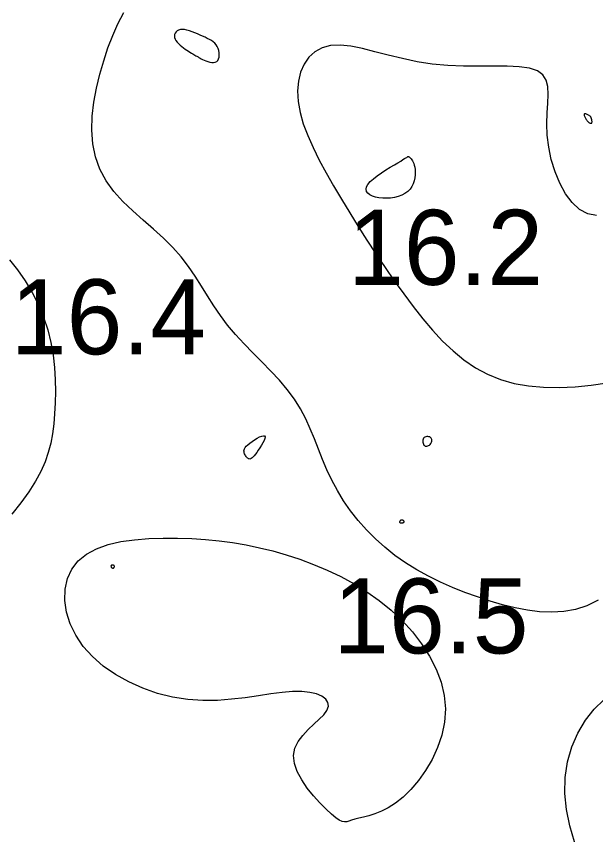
# Model space of a CAD drawing. Extents: x 3040093 to 3056816, y 408076 to 509144.
# Drawn here: x 3045557.4 to 3045596, y 434288.8 to 434343.4 of the extents above; entities that cross this region are included whole.
import ezdxf

# ---------------------------------------------------------------- set-up
doc = ezdxf.new("R2010")
doc.units = 0
doc.layers.add('V-CHAN-CONT-EL17', color=7, linetype='Continuous')
doc.layers.add('V-TOPO-SOUN-0610', color=7, linetype='Continuous')

msp = doc.modelspace()

# ---------------------------------------------------------------- linework, layer by layer
at = {"layer": 'V-CHAN-CONT-EL17'}
for points in [[(3045596.195, 434304.462), (3045595.445, 434304.104), (3045594.676, 434303.857), (3045593.893, 434303.714), (3045593.097, 434303.664), (3045592.29, 434303.696), (3045591.474, 434303.798), (3045590.65, 434303.959), (3045589.819, 434304.168), (3045588.984, 434304.414), (3045588.148, 434304.688), (3045587.313, 434304.989), (3045586.487, 434305.32), (3045585.673, 434305.68), (3045584.877, 434306.073), (3045584.104, 434306.499), (3045583.359, 434306.961), (3045582.648, 434307.459), (3045581.974, 434307.995), (3045581.34, 434308.565), (3045580.747, 434309.165), (3045580.196, 434309.79), (3045579.689, 434310.437), (3045579.226, 434311.1), (3045578.809, 434311.776), (3045578.44, 434312.461), (3045578.116, 434313.15), (3045577.825, 434313.84), (3045577.553, 434314.53), (3045577.285, 434315.216), (3045577.004, 434315.896), (3045576.697, 434316.568), (3045576.348, 434317.228), (3045575.942, 434317.875), (3045575.47, 434318.508), (3045574.942, 434319.128), (3045574.374, 434319.74), (3045573.782, 434320.347), (3045573.182, 434320.953), (3045572.589, 434321.563), (3045572.021, 434322.179), (3045571.492, 434322.806), (3045571.013, 434323.446), (3045570.573, 434324.096), (3045570.156, 434324.752), (3045569.746, 434325.41), (3045569.325, 434326.067), (3045568.878, 434326.717), (3045568.388, 434327.358), (3045567.839, 434327.984), (3045567.221, 434328.594), (3045566.553, 434329.196), (3045565.862, 434329.799), (3045565.174, 434330.415), (3045564.514, 434331.052), (3045563.91, 434331.722), (3045563.386, 434332.433), (3045562.97, 434333.196), (3045562.68, 434334.018), (3045562.51, 434334.889), (3045562.445, 434335.796), (3045562.473, 434336.727), (3045562.579, 434337.669), (3045562.751, 434338.609), (3045562.973, 434339.534), (3045563.232, 434340.432), (3045563.518, 434341.291), (3045563.833, 434342.113), (3045564.18, 434342.898), (3045564.564, 434343.649)], [(3045596.085, 434330.119), (3045595.494, 434330.23), (3045594.949, 434330.522), (3045594.454, 434330.977), (3045594.014, 434331.567), (3045593.634, 434332.259), (3045593.318, 434333.026), (3045593.069, 434333.836), (3045592.892, 434334.66), (3045592.792, 434335.467), (3045592.766, 434336.233), (3045592.789, 434336.945), (3045592.828, 434337.599), (3045592.851, 434338.187), (3045592.826, 434338.703), (3045592.721, 434339.141), (3045592.503, 434339.495), (3045592.142, 434339.757), (3045591.613, 434339.927), (3045590.934, 434340.02), (3045590.13, 434340.06), (3045589.226, 434340.066), (3045588.25, 434340.062), (3045587.225, 434340.068), (3045586.179, 434340.106), (3045585.137, 434340.198), (3045584.122, 434340.357), (3045583.142, 434340.566), (3045582.204, 434340.799), (3045581.313, 434341.032), (3045580.477, 434341.237), (3045579.7, 434341.392), (3045578.988, 434341.468), (3045578.349, 434341.442), (3045577.786, 434341.295), (3045577.303, 434341.031), (3045576.902, 434340.665), (3045576.585, 434340.207), (3045576.353, 434339.67), (3045576.21, 434339.068), (3045576.156, 434338.411), (3045576.194, 434337.713), (3045576.323, 434336.984), (3045576.538, 434336.227), (3045576.828, 434335.444), (3045577.184, 434334.637), (3045577.596, 434333.807), (3045578.057, 434332.956), (3045578.555, 434332.086), (3045579.083, 434331.198), (3045579.631, 434330.294), (3045580.198, 434329.381), (3045580.78, 434328.463), (3045581.376, 434327.549), (3045581.985, 434326.642), (3045582.603, 434325.751), (3045583.231, 434324.881), (3045583.865, 434324.038), (3045584.505, 434323.228), (3045585.156, 434322.461), (3045585.825, 434321.742), (3045586.519, 434321.082), (3045587.244, 434320.486), (3045588.008, 434319.965), (3045588.816, 434319.525), (3045589.675, 434319.175), (3045590.59, 434318.92), (3045591.554, 434318.754), (3045592.558, 434318.668), (3045593.594, 434318.653), (3045594.652, 434318.701), (3045595.724, 434318.803), (3045596.801, 434318.95)], [(3045556.955, 434327.16), (3045557.493, 434326.486), (3045558.002, 434325.753), (3045558.468, 434324.974), (3045558.882, 434324.162), (3045559.231, 434323.33), (3045559.507, 434322.488), (3045559.715, 434321.645), (3045559.862, 434320.807), (3045559.957, 434319.979), (3045560.006, 434319.169), (3045560.018, 434318.381), (3045559.999, 434317.624), (3045559.958, 434316.902), (3045559.9, 434316.22), (3045559.817, 434315.568), (3045559.7, 434314.937), (3045559.537, 434314.316), (3045559.321, 434313.692), (3045559.04, 434313.056), (3045558.685, 434312.396), (3045558.245, 434311.701), (3045557.716, 434310.967), (3045557.11, 434310.212)], [(3045596.55, 434284.32), (3045596.002, 434285.266), (3045595.487, 434286.261), (3045595.02, 434287.294), (3045594.619, 434288.355), (3045594.298, 434289.432), (3045594.075, 434290.516), (3045593.965, 434291.595), (3045593.985, 434292.659), (3045594.146, 434293.696), (3045594.436, 434294.688), (3045594.841, 434295.616), (3045595.343, 434296.463), (3045595.927, 434297.209), (3045596.577, 434297.835)]]:
    msp.add_lwpolyline(points, dxfattribs=at)
for points in [[(3045569.928, 434340.473), (3045570.046, 434340.424), (3045570.174, 434340.378), (3045570.306, 434340.339), (3045570.437, 434340.314), (3045570.561, 434340.306), (3045570.673, 434340.322), (3045570.768, 434340.366), (3045570.842, 434340.442), (3045570.894, 434340.545), (3045570.925, 434340.669), (3045570.936, 434340.807), (3045570.928, 434340.953), (3045570.902, 434341.101), (3045570.859, 434341.245), (3045570.799, 434341.377), (3045570.723, 434341.494), (3045570.633, 434341.596), (3045570.529, 434341.687), (3045570.411, 434341.769), (3045570.281, 434341.844), (3045570.14, 434341.916), (3045569.988, 434341.988), (3045569.827, 434342.062), (3045569.657, 434342.139), (3045569.482, 434342.218), (3045569.303, 434342.295), (3045569.125, 434342.365), (3045568.95, 434342.426), (3045568.782, 434342.474), (3045568.622, 434342.504), (3045568.475, 434342.514), (3045568.343, 434342.501), (3045568.228, 434342.466), (3045568.13, 434342.413), (3045568.052, 434342.344), (3045567.994, 434342.263), (3045567.958, 434342.172), (3045567.945, 434342.075), (3045567.956, 434341.973), (3045567.992, 434341.871), (3045568.051, 434341.769), (3045568.127, 434341.668), (3045568.219, 434341.568), (3045568.322, 434341.472), (3045568.432, 434341.379), (3045568.546, 434341.291), (3045568.66, 434341.209), (3045568.772, 434341.133), (3045568.879, 434341.063), (3045568.981, 434340.999), (3045569.077, 434340.941), (3045569.165, 434340.889), (3045569.246, 434340.843), (3045569.318, 434340.801), (3045569.381, 434340.765), (3045569.433, 434340.734), (3045569.479, 434340.705), (3045569.522, 434340.679), (3045569.565, 434340.653), (3045569.613, 434340.625), (3045569.67, 434340.595), (3045569.739, 434340.561), (3045569.824, 434340.52)], [(3045595.778, 434336.32), (3045595.782, 434336.351), (3045595.781, 434336.386), (3045595.778, 434336.424), (3045595.771, 434336.463), (3045595.763, 434336.503), (3045595.754, 434336.542), (3045595.743, 434336.578), (3045595.733, 434336.61), (3045595.721, 434336.639), (3045595.707, 434336.666), (3045595.692, 434336.69), (3045595.672, 434336.713), (3045595.649, 434336.736), (3045595.621, 434336.758), (3045595.588, 434336.78), (3045595.548, 434336.803), (3045595.505, 434336.826), (3045595.459, 434336.847), (3045595.413, 434336.866), (3045595.369, 434336.879), (3045595.33, 434336.888), (3045595.296, 434336.888), (3045595.271, 434336.881), (3045595.255, 434336.864), (3045595.249, 434336.839), (3045595.251, 434336.807), (3045595.26, 434336.769), (3045595.275, 434336.727), (3045595.294, 434336.683), (3045595.317, 434336.637), (3045595.343, 434336.592), (3045595.37, 434336.548), (3045595.398, 434336.506), (3045595.427, 434336.466), (3045595.457, 434336.429), (3045595.487, 434336.394), (3045595.518, 434336.363), (3045595.549, 434336.335), (3045595.58, 434336.311), (3045595.611, 434336.291), (3045595.641, 434336.276), (3045595.669, 434336.265), (3045595.696, 434336.259), (3045595.72, 434336.259), (3045595.741, 434336.264), (3045595.758, 434336.276), (3045595.77, 434336.295)], [(3045580.991, 434332.368), (3045581.206, 434332.562), (3045581.463, 434332.76), (3045581.747, 434332.957), (3045582.042, 434333.148), (3045582.333, 434333.327), (3045582.605, 434333.49), (3045582.843, 434333.63), (3045583.034, 434333.744), (3045583.182, 434333.834), (3045583.293, 434333.903), (3045583.372, 434333.954), (3045583.427, 434333.989), (3045583.463, 434334.012), (3045583.487, 434334.027), (3045583.504, 434334.035), (3045583.52, 434334.04), (3045583.537, 434334.041), (3045583.556, 434334.038), (3045583.576, 434334.029), (3045583.599, 434334.015), (3045583.625, 434333.993), (3045583.655, 434333.964), (3045583.69, 434333.927), (3045583.729, 434333.88), (3045583.772, 434333.823), (3045583.816, 434333.754), (3045583.859, 434333.671), (3045583.9, 434333.573), (3045583.936, 434333.459), (3045583.965, 434333.326), (3045583.985, 434333.175), (3045583.994, 434333.003), (3045583.99, 434332.817), (3045583.968, 434332.621), (3045583.927, 434332.422), (3045583.862, 434332.224), (3045583.772, 434332.034), (3045583.652, 434331.858), (3045583.5, 434331.701), (3045583.313, 434331.568), (3045583.099, 434331.459), (3045582.862, 434331.374), (3045582.609, 434331.312), (3045582.349, 434331.273), (3045582.086, 434331.257), (3045581.828, 434331.262), (3045581.581, 434331.289), (3045581.353, 434331.336), (3045581.149, 434331.403), (3045580.978, 434331.49), (3045580.845, 434331.595), (3045580.757, 434331.717), (3045580.721, 434331.857), (3045580.744, 434332.012), (3045580.833, 434332.183)], [(3045573.342, 434314.2), (3045573.26, 434314.099), (3045573.187, 434314.019), (3045573.122, 434313.958), (3045573.065, 434313.916), (3045573.012, 434313.891), (3045572.964, 434313.881), (3045572.919, 434313.885), (3045572.875, 434313.901), (3045572.833, 434313.928), (3045572.793, 434313.964), (3045572.755, 434314.008), (3045572.72, 434314.058), (3045572.686, 434314.113), (3045572.656, 434314.17), (3045572.628, 434314.23), (3045572.604, 434314.289), (3045572.587, 434314.351), (3045572.58, 434314.415), (3045572.588, 434314.483), (3045572.613, 434314.558), (3045572.661, 434314.639), (3045572.734, 434314.73), (3045572.837, 434314.83), (3045572.97, 434314.941), (3045573.126, 434315.057), (3045573.294, 434315.169), (3045573.464, 434315.27), (3045573.626, 434315.352), (3045573.769, 434315.409), (3045573.883, 434315.433), (3045573.957, 434315.416), (3045573.985, 434315.353), (3045573.97, 434315.252), (3045573.922, 434315.12), (3045573.847, 434314.966), (3045573.753, 434314.801), (3045573.647, 434314.633), (3045573.539, 434314.471), (3045573.435, 434314.324)], [(3045585.067, 434314.958), (3045585.091, 434315.014), (3045585.105, 434315.072), (3045585.11, 434315.129), (3045585.104, 434315.183), (3045585.088, 434315.234), (3045585.06, 434315.28), (3045585.02, 434315.318), (3045584.969, 434315.348), (3045584.91, 434315.368), (3045584.844, 434315.378), (3045584.777, 434315.378), (3045584.71, 434315.367), (3045584.648, 434315.346), (3045584.593, 434315.313), (3045584.549, 434315.267), (3045584.518, 434315.211), (3045584.501, 434315.145), (3045584.496, 434315.074), (3045584.502, 434315.002), (3045584.519, 434314.932), (3045584.545, 434314.868), (3045584.579, 434314.813), (3045584.621, 434314.771), (3045584.67, 434314.745), (3045584.723, 434314.735), (3045584.779, 434314.738), (3045584.835, 434314.753), (3045584.891, 434314.778), (3045584.944, 434314.813), (3045584.992, 434314.856), (3045585.033, 434314.904)], [(3045583.26, 434309.707), (3045583.256, 434309.718), (3045583.25, 434309.73), (3045583.243, 434309.741), (3045583.233, 434309.753), (3045583.222, 434309.765), (3045583.208, 434309.776), (3045583.192, 434309.786), (3045583.173, 434309.795), (3045583.153, 434309.803), (3045583.131, 434309.809), (3045583.108, 434309.812), (3045583.085, 434309.812), (3045583.063, 434309.809), (3045583.041, 434309.803), (3045583.02, 434309.792), (3045583.002, 434309.776), (3045582.986, 434309.757), (3045582.973, 434309.736), (3045582.964, 434309.714), (3045582.959, 434309.692), (3045582.96, 434309.671), (3045582.966, 434309.653), (3045582.979, 434309.638), (3045582.998, 434309.628), (3045583.022, 434309.623), (3045583.05, 434309.621), (3045583.081, 434309.622), (3045583.113, 434309.626), (3045583.144, 434309.631), (3045583.173, 434309.637), (3045583.199, 434309.643), (3045583.219, 434309.649), (3045583.236, 434309.655), (3045583.248, 434309.661), (3045583.256, 434309.667), (3045583.261, 434309.674), (3045583.264, 434309.681), (3045583.264, 434309.688), (3045583.263, 434309.697)], [(3045575.969, 434294.598), (3045576.187, 434295.047), (3045576.495, 434295.461), (3045576.857, 434295.844), (3045577.237, 434296.199), (3045577.598, 434296.529), (3045577.903, 434296.838), (3045578.116, 434297.128), (3045578.208, 434297.4), (3045578.178, 434297.651), (3045578.032, 434297.875), (3045577.779, 434298.066), (3045577.424, 434298.218), (3045576.974, 434298.325), (3045576.436, 434298.381), (3045575.817, 434298.38), (3045575.123, 434298.321), (3045574.362, 434298.22), (3045573.543, 434298.096), (3045572.672, 434297.97), (3045571.758, 434297.862), (3045570.808, 434297.792), (3045569.831, 434297.779), (3045568.833, 434297.845), (3045567.825, 434298.005), (3045566.822, 434298.258), (3045565.841, 434298.597), (3045564.899, 434299.017), (3045564.013, 434299.513), (3045563.2, 434300.078), (3045562.476, 434300.707), (3045561.86, 434301.393), (3045561.365, 434302.13), (3045560.996, 434302.899), (3045560.754, 434303.68), (3045560.641, 434304.456), (3045560.66, 434305.204), (3045560.812, 434305.907), (3045561.098, 434306.544), (3045561.521, 434307.096), (3045562.079, 434307.547), (3045562.755, 434307.904), (3045563.529, 434308.175), (3045564.381, 434308.371), (3045565.29, 434308.503), (3045566.237, 434308.578), (3045567.2, 434308.609), (3045568.161, 434308.604), (3045569.102, 434308.572), (3045570.024, 434308.512), (3045570.931, 434308.424), (3045571.828, 434308.305), (3045572.719, 434308.154), (3045573.608, 434307.97), (3045574.501, 434307.749), (3045575.4, 434307.492), (3045576.309, 434307.196), (3045577.223, 434306.858), (3045578.133, 434306.476), (3045579.034, 434306.047), (3045579.917, 434305.569), (3045580.776, 434305.038), (3045581.603, 434304.454), (3045582.39, 434303.812), (3045583.131, 434303.112), (3045583.813, 434302.36), (3045584.425, 434301.565), (3045584.955, 434300.734), (3045585.39, 434299.877), (3045585.719, 434299.001), (3045585.93, 434298.114), (3045586.009, 434297.225), (3045585.952, 434296.342), (3045585.771, 434295.477), (3045585.487, 434294.643), (3045585.118, 434293.851), (3045584.684, 434293.113), (3045584.205, 434292.442), (3045583.699, 434291.85), (3045583.187, 434291.35), (3045582.684, 434290.948), (3045582.2, 434290.636), (3045581.739, 434290.4), (3045581.307, 434290.226), (3045580.908, 434290.1), (3045580.549, 434290.008), (3045580.234, 434289.937), (3045579.969, 434289.873), (3045579.756, 434289.805), (3045579.582, 434289.744), (3045579.43, 434289.701), (3045579.282, 434289.689), (3045579.124, 434289.722), (3045578.938, 434289.811), (3045578.708, 434289.97), (3045578.416, 434290.212), (3045578.054, 434290.544), (3045577.645, 434290.955), (3045577.218, 434291.427), (3045576.804, 434291.943), (3045576.433, 434292.487), (3045576.135, 434293.041), (3045575.94, 434293.588), (3045575.878, 434294.112)], [(3045563.91, 434306.784), (3045563.892, 434306.794), (3045563.87, 434306.803), (3045563.847, 434306.809), (3045563.824, 434306.813), (3045563.801, 434306.814), (3045563.78, 434306.812), (3045563.761, 434306.806), (3045563.746, 434306.796), (3045563.734, 434306.783), (3045563.725, 434306.767), (3045563.721, 434306.75), (3045563.719, 434306.731), (3045563.721, 434306.711), (3045563.726, 434306.692), (3045563.734, 434306.674), (3045563.746, 434306.657), (3045563.759, 434306.642), (3045563.775, 434306.629), (3045563.792, 434306.618), (3045563.809, 434306.61), (3045563.827, 434306.603), (3045563.844, 434306.6), (3045563.859, 434306.599), (3045563.873, 434306.6), (3045563.885, 434306.605), (3045563.895, 434306.611), (3045563.904, 434306.619), (3045563.912, 434306.629), (3045563.919, 434306.641), (3045563.926, 434306.653), (3045563.932, 434306.666), (3045563.938, 434306.679), (3045563.943, 434306.693), (3045563.946, 434306.707), (3045563.948, 434306.721), (3045563.947, 434306.734), (3045563.944, 434306.748), (3045563.937, 434306.76), (3045563.926, 434306.773)]]:
    msp.add_lwpolyline(points, close=True, dxfattribs=at)

# ---------------------------------------------------------------- texts
at = {"layer": 'V-TOPO-SOUN-0610'}
for s, p in [('16.2 ', (3045579.513, 434325.49)), ('16.4 ', (3045557.043, 434320.86)), ('16.5 ', (3045578.533, 434300.92))]:
    msp.add_text(s, height=5, dxfattribs=at).set_placement(p)

doc.saveas('drawing.dxf')
